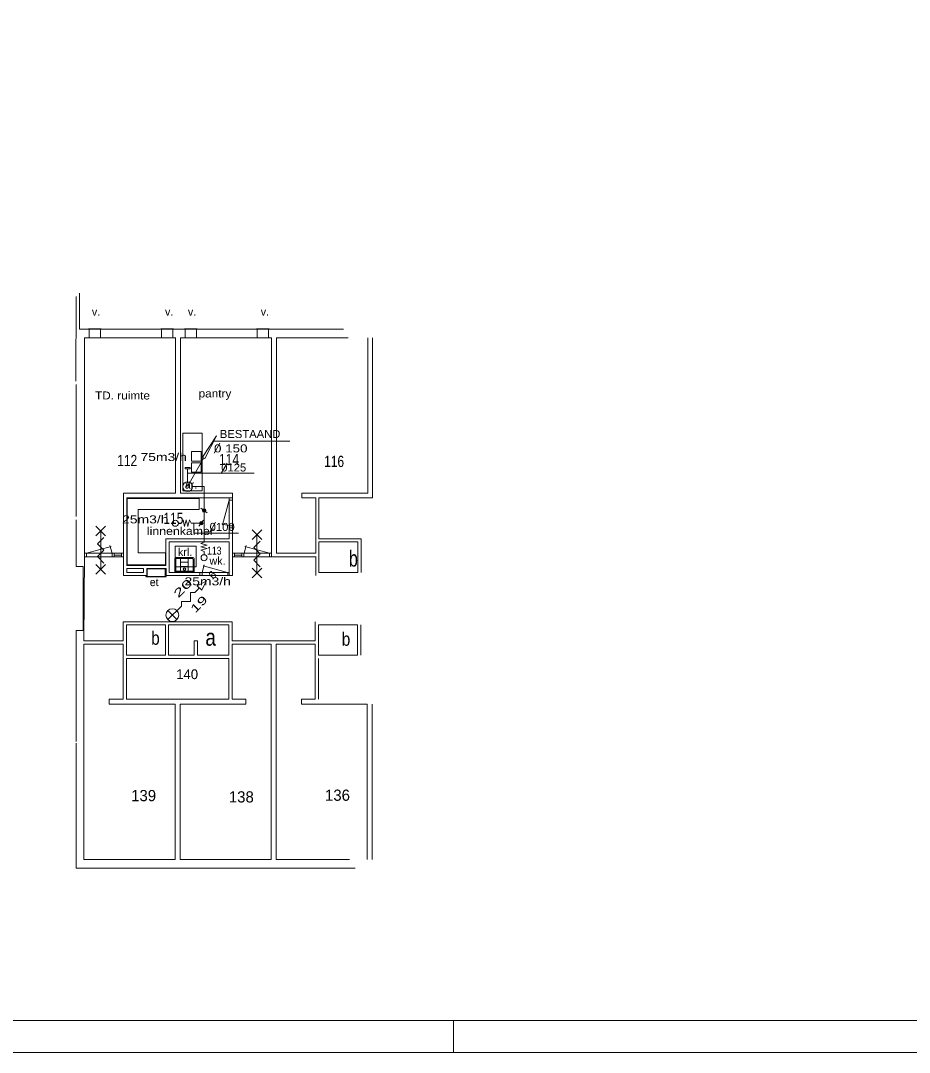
# Model space of a CAD drawing. Extents: x 295824 to 414724, y 24924 to 109024.
# Drawn here: x 359197 to 386960, y 24924 to 57152 of the extents above; entities that cross this region are included whole.
import ezdxf
from ezdxf.enums import TextEntityAlignment as Align

# ---------------------------------------------------------------- set-up
doc = ezdxf.new("R2010")
doc.units = 0
doc.header["$LTSCALE"] = 100
for name, color, linetype, lineweight in [('1', 7, 'Continuous', 13), ('24', 7, 'Continuous', 13), ('61', 7, 'Continuous', 13)]:
    doc.layers.add(name, color=color, linetype=linetype, lineweight=lineweight)

msp = doc.modelspace()

# ---------------------------------------------------------------- hatches: boundary and pattern name
at = {"layer": '24'}
for points in [[(364874.8, 41850, 1), (364983.4, 41850, 1)], [(364839.5, 41507.5, 1), (364839.5, 41398.9, 1)]]:
    msp.add_hatch(color=256, dxfattribs=at).paths.add_polyline_path(points)

# ---------------------------------------------------------------- linework, layer by layer
at = {"layer": '1'}
for p, q in [((364417.5, 42624), (364917.5, 43490)), ((372723.6, 24923.8), (372723.6, 25923.8)), ((304995.6, 24923.8), (414723.6, 24923.8))]:
    msp.add_line(p, q, dxfattribs=at)
msp.add_lwpolyline([(304995.6, 25923.8), (413723.6, 25923.8), (413723.6, 108023.8), (304995.6, 108023.8)], dxfattribs=at)
msp.add_lwpolyline([(365317.5, 44183), (364953.5, 43469), (364881.5, 43511)], close=True, dxfattribs=at)
msp.add_circle((364417.5, 42623.6), 50, dxfattribs=at)
at = {"layer": '24'}
for p, q in [((365423.5, 43957.8), (365239.1, 43638.5)), ((365240.5, 44010.8), (367601.3, 44010.8)), ((365649.4, 43330), (365465, 43010.7)), ((364412.7, 42748.9), (364412.7, 43166.1)), ((364431.5, 43018.1), (366491.3, 43018.1)), ((364566.3, 42595.3), (364929.1, 42595.3)), ((364929.1, 40914.6), (364929.1, 42595.3)), ((365020.7, 41779.2), (364829.1, 41920.8)), ((364570.4, 41453.2), (364929.1, 41453.2)), ((364768.7, 41361.6), (364910.3, 41553.1)), ((365287.7, 41489), (365103.4, 41169.7))]:
    msp.add_line(p, q, dxfattribs=at)
msp.add_lwpolyline([(364496.8, 43150.3), (364496.8, 43193.8), (364334.5, 43193.8), (364334.5, 43150.3)], close=True, dxfattribs=at)
for points in [[(364120.4, 41453.2), (364220.4, 41453.2), (364270.4, 41553.2), (364320.4, 41353.2), (364370.4, 41553.2), (364420.4, 41353.2), (364470.4, 41553.2), (364520.4, 41453.2), (364570.4, 41453.2)], [(364604.5, 41460.4), (364604.5, 41145.7), (366003.9, 41145.7)], [(364929.1, 40464.6), (364929.1, 40564.6), (364829.1, 40614.6), (365029.1, 40664.6), (364829.1, 40714.6), (365029.1, 40764.6), (364829.1, 40814.6), (364929.1, 40864.6), (364929.1, 40914.6)]]:
    msp.add_lwpolyline(points, dxfattribs=at)
for centre, radius in [((364412.7, 42595.3), 153.6), ((364929.1, 41850), 54.3), ((364028.7, 41453.2), 95), ((364839.5, 41453.2), 54.3), ((364929.1, 40372.9), 95)]:
    msp.add_circle(centre, radius, dxfattribs=at)
at = {"layer": '61'}
for p, q in [((360918.7, 45887.9), (360931.7, 48537.9)), ((361031.7, 48637.9), (361031.7, 47511.4)), ((361031.7, 47511.4), (369284.8, 47511.4)), ((361708, 47527.5), (361314.8, 47527.5)), ((361314.8, 47527.5), (361314.8, 47510)), ((361708, 47510), (361314.8, 47510)), ((361338.9, 47510), (361338.9, 47238.9)), ((361688.9, 47507.7), (361688.9, 47238.9)), ((361708, 47527.5), (361708, 47510)), ((363970.3, 47527.5), (363577.1, 47527.5)), ((363577.1, 47527.5), (363577.1, 47510)), ((363970.3, 47510), (363577.1, 47510)), ((363601.1, 47510), (363601.1, 47238.9)), ((363951.1, 47507.8), (363951.1, 47238.9)), ((363970.3, 47527.5), (363970.3, 47510)), ((364708.8, 47527.5), (364315.6, 47527.5)), ((364315.6, 47527.5), (364315.6, 47510)), ((364708.8, 47510), (364315.6, 47510)), ((364339.6, 47510), (364339.6, 47238.9)), ((364689.6, 47507.7), (364689.6, 47238.9)), ((364708.8, 47527.5), (364708.8, 47510)), ((366959.9, 47527.5), (366566.7, 47527.5)), ((366566.7, 47527.5), (366566.7, 47510)), ((366959.9, 47510), (366566.7, 47510)), ((366590.7, 47510), (366590.7, 47238.9)), ((366940.7, 47507.8), (366940.7, 47238.9)), ((366959.9, 47527.5), (366959.9, 47510)), ((361187.9, 47241.4), (361787.9, 47241.4)), ((361188.7, 40516.4), (361188.7, 47241.4)), ((363449.6, 47241.4), (364049, 47241.4)), ((363961.5, 47238.9), (363568.3, 47238.9)), ((367038.7, 47238.9), (364306.8, 47238.9)), ((367038.7, 47241.4), (364888.7, 47241.4)), ((366439.2, 47241.4), (367038.7, 47241.4)), ((366951.2, 47238.9), (366558, 47238.9)), ((367038.7, 40405.5), (367038.7, 47238.9)), ((367188.7, 47241.4), (369431.5, 47241.4)), ((370188.7, 47241.4), (370188.7, 42241.3)), ((360931.7, 45787.9), (360931.7, 41658.1)), ((362513.7, 42241.4), (365813.7, 42241.4)), ((362513.7, 40136.4), (362513.7, 42241.4)), ((364188.7, 42391.4), (365813.7, 42391.4)), ((364266.1, 42467.5), (364863.2, 42467.5)), ((365813.3, 42241.4), (365713.7, 42241.4)), ((365713.7, 42241.4), (365713.7, 40966.4)), ((365813.3, 42241.4), (365813.3, 41307.4)), ((365813.7, 42391.4), (365813.7, 42241.4)), ((368513.7, 40963.7), (368513.7, 42241.3)), ((370188.7, 42241.3), (368513.7, 42241.3)), ((365713.6, 42170.8), (365506.7, 41398.6)), ((365813.5, 42174.4), (365713.3, 42174.4)), ((361848.8, 41358), (361548.8, 41058)), ((361548.8, 41358), (361848.8, 41058)), ((365713.6, 41373.3), (365486.3, 41434.2)), ((365713.3, 41307.4), (365713.3, 41305.7)), ((365813.7, 41307.4), (365713.3, 41307.4)), ((365813.2, 41374.4), (365713.9, 41374.4)), ((365813.7, 41307.4), (365813.7, 40516.4)), ((361698.8, 40008), (361698.8, 41208)), ((365713.7, 40966.4), (363733.7, 40966.4)), ((363733.7, 40966.4), (363733.7, 40136.4)), ((366729.4, 41244.4), (366429.4, 40944.4)), ((366429.4, 41244.4), (366729.4, 40944.4)), ((366579.4, 39894.4), (366579.4, 41094.4)), ((368513.7, 40963.7), (369833.7, 40963.7)), ((369833.7, 39916.4), (369833.7, 40963.7)), ((361258.1, 40516.3), (362025.4, 40721.9)), ((362052.7, 40514.1), (361987.6, 40756.9)), ((364023.8, 40085.7), (364023.8, 40735.7)), ((364028.2, 40735.5), (364678.2, 40735.5)), ((364676.5, 40085.7), (364676.5, 40735.7)), ((366174.8, 40513.3), (366239.8, 40756.1)), ((366969.4, 40515.5), (366202.1, 40721.1)), ((361255.5, 40406.1), (361255.5, 40516.1)), ((362055.5, 40406.1), (362055.5, 40516.1)), ((362122.5, 40406.1), (362122.5, 40516.1)), ((362123.3, 40456.9), (362348, 40456.9)), ((362348, 40406.1), (362348, 40516.1)), ((362413.7, 40406.4), (362413.7, 39816.4)), ((364010.2, 40345.4), (364010.2, 39930.4)), ((364585.2, 40380.4), (364045.2, 40380.4)), ((364045.2, 39970.4), (364045.2, 40330.4)), ((364060.2, 40345.4), (364570.2, 40345.4)), ((364195.2, 39955.4), (364195.2, 40380.4)), ((364435.2, 39955.4), (364435.2, 40380.4)), ((364585.2, 40330.4), (364585.2, 39970.4)), ((364620.2, 39930.4), (364620.2, 40345.4)), ((365813.7, 39816.4), (365813.7, 40416.4)), ((365879.5, 40405.3), (365879.5, 40515.3)), ((366104.1, 40456.1), (365879.5, 40456.1)), ((366105, 40405.3), (366105, 40515.3)), ((366172, 40405.3), (366172, 40515.3)), ((366972, 40405.3), (366972, 40515.3)), ((367038.7, 40405.5), (368413.7, 40405.5)), ((368413.7, 40416.4), (368413.7, 39816.4)), ((361848.8, 40158), (361548.8, 39858)), ((361548.8, 40158), (361848.8, 39858)), ((363733.7, 40136.4), (362513.7, 40136.4)), ((362513.7, 39916.4), (362513.7, 40036.4)), ((363033.7, 40036.4), (362513.7, 40036.4)), ((363033.7, 40036.4), (363033.7, 39916.4)), ((363138, 40043), (363138, 39816.4)), ((363738, 40043), (363138, 40043)), ((363148.8, 39792.7), (363148.8, 40027.7)), ((363148.8, 40027.7), (363714.2, 40027.7)), ((363714.2, 39792.6), (363714.2, 40027.7)), ((363738, 40043), (363738, 39816.4)), ((364028.2, 40086.8), (364678.2, 40086.8)), ((364435.2, 40238.8), (364195.2, 40238.8)), ((364435.2, 40097.1), (364195.2, 40097.1)), ((364868.2, 39913.8), (364933.2, 40156.6)), ((365662.8, 39916), (364895.5, 40121.6)), ((366729.4, 40044.4), (366429.4, 39744.4)), ((366429.4, 40044.4), (366729.4, 39744.4)), ((362413.7, 39816.4), (363138, 39816.4)), ((362513.7, 39916.4), (363033.7, 39916.4)), ((363109.5, 39792.7), (363740.8, 39792.7)), ((363109.5, 39775.2), (363109.5, 39792.7)), ((363109.5, 39775.2), (363740.8, 39775.2)), ((363738, 39816.4), (365813.7, 39816.4)), ((363740.8, 39775.2), (363740.8, 39792.7)), ((364610.2, 39955.4), (364020.2, 39955.4)), ((364020.2, 39920.4), (364610.2, 39920.4)), ((364798.4, 39816.5), (364798.4, 39915.8)), ((364865.4, 39819.9), (364865.4, 39915.8)), ((365665.4, 39816.5), (365665.4, 39915.8)), ((363795.3, 38723), (364078.1, 38440.2)), ((369820.9, 38277.1), (369820.9, 37327.1)), ((368500.9, 37227.1), (368500.9, 35952.1)), ((370175.9, 30952.1), (370175.9, 35802.1)), ((360931.7, 30682.1), (360931.7, 34578.2)), ((367175.9, 30952.1), (369468.2, 30952.1)), ((369651.6, 30682.1), (360931.7, 30682.1))]:
    msp.add_line(p, q, dxfattribs=at)
for points in [[(361188.7, 47241.4), (364038.7, 47241.4), (364038.7, 42391.4), (362413.7, 42391.4), (362413.7, 40516.9)], [(364188.7, 42391.4), (364188.7, 47241.4), (364788.7, 47241.4)], [(370038.7, 47241.4), (370038.7, 42391.4), (367978.7, 42391.4), (367978.7, 42241.4), (368413.7, 42241.4), (368413.7, 40516.4), (367188.7, 40516.4), (367188.7, 47241.4)], [(364863.2, 42467.5), (364863.2, 44267.5), (364263.2, 44267.5), (364263.2, 42474.2)], [(360931.7, 41558.1), (360931.7, 40096.8), (361151.7, 40096.8), (361151.7, 38096.8), (360931.7, 38096.8), (360931.7, 34630.7)], [(361798.8, 40208), (361598.8, 40408), (361798.8, 40608), (361598.8, 40808), (361798.8, 41008)], [(363833.7, 40866.4), (365713.7, 40866.4), (365713.7, 39816.4)], [(365713.7, 39916.4), (363833.7, 39916.4), (363833.7, 40866.4)], [(366679.4, 40094.4), (366479.4, 40294.4), (366679.4, 40494.4), (366479.4, 40694.4), (366679.4, 40894.4)], [(368400.9, 38377.1), (368400.9, 37777.1), (365800.9, 37777.1), (365800.9, 38377.1), (362400.9, 38377.1), (362400.9, 37777.1), (361175.9, 37777.1), (361188.7, 40416.4)], [(363795.3, 38440.2), (364219.6, 38864.4), (364219.6, 39005.8), (364502.4, 39005.8), (364502.4, 39288.7), (364643.8, 39288.7), (364785.2, 39430.1)], [(370025.9, 30952.1), (370025.9, 35802.1), (367965.9, 35802.1), (367965.9, 35952.1), (368400.9, 35952.1), (368400.9, 37677.1), (367175.9, 37677.1), (367175.9, 30952.1)]]:
    msp.add_lwpolyline(points, dxfattribs=at)
for points in [[(364838.2, 43392.5), (364838.2, 43692.5), (364538.2, 43692.5), (364538.2, 43392.5)], [(364838.2, 43042.2), (364838.2, 43342.2), (364538.2, 43342.2), (364538.2, 43042.2)], [(364776.8, 42220.8), (364776.8, 41876.1), (362865.2, 41876.1), (362865.2, 40530.5), (363723.5, 40530.5), (363723.5, 40149.7), (362523.5, 40149.7), (362523.5, 42220.8)], [(368513.7, 40866.4), (369733.7, 40866.4), (369733.7, 39916.4), (368513.7, 39916.4)], [(361189.6, 40406.5), (361189.6, 40516.9), (362413.9, 40516.9), (362413.9, 40406.5)], [(367037.9, 40405.7), (367037.9, 40516.1), (365813.5, 40516.1), (365813.5, 40405.7)], [(364856, 39359.4), (364714.5, 39500.8), (364997.4, 39642.2)], [(362500.9, 37327.1), (363720.9, 37327.1), (363720.9, 38277.1), (362500.9, 38277.1)], [(363820.9, 37327.1), (364620.9, 37327.1), (364620.9, 37777.1), (364720.9, 37777.1), (364720.9, 37327.1), (365700.9, 37327.1), (365700.9, 38277.1), (363820.9, 38277.1)], [(368500.9, 37327.1), (369720.9, 37327.1), (369720.9, 38277.1), (368500.9, 38277.1)], [(361175.9, 30952.1), (364025.9, 30952.1), (364025.9, 35802.1), (361965.9, 35802.1), (361965.9, 35952.1), (362400.9, 35952.1), (362400.9, 37677.1), (361175.9, 37677.1)], [(367025.9, 30952.1), (364175.9, 30952.1), (364175.9, 35802.1), (366235.9, 35802.1), (366235.9, 35952.1), (365800.9, 35952.1), (365800.9, 37677.1), (367025.9, 37677.1)], [(362500.9, 35952.1), (365700.9, 35952.1), (365700.9, 37227.1), (362500.9, 37227.1)]]:
    msp.add_lwpolyline(points, close=True, dxfattribs=at)
for centre, radius in [((364315.2, 40020.4), 40), ((364315.2, 40020.4), 30), ((363936.7, 38581.6), 200)]:
    msp.add_circle(centre, radius, dxfattribs=at)
for centre, radius, start, end in [((364045.2, 40345.4), 35, 90, 180), ((364060.2, 40330.4), 15, 90, 180), ((364570.2, 40330.4), 15, 0, 90), ((364585.2, 40345.4), 35, 0, 90), ((364060.2, 39970.4), 15, 180, 270), ((364570.2, 39970.4), 15, 270, 0), ((364020.2, 39945.4), 10, 90, 180), ((364020.2, 39930.4), 10, 180, 270), ((364610.2, 39945.4), 10, 0, 90), ((364610.2, 39930.4), 10, 270, 0)]:
    msp.add_arc(centre, radius, start, end, dxfattribs=at)

# ---------------------------------------------------------------- texts
at = {"layer": '24'}
for s, width, p in [('BESTAAND', 1.05, (365419.2, 44114.8)), ('0 150', 1.25, (365237.4, 43664.8)), ('75m3/h', 1.3, (362941.1, 43395.8)), ('0125', 1.05, (365463.3, 43068.5)), ('25m3/h', 1.3, (362365.7, 41447.8)), ('0100', 1.05, (365101.6, 41211.8)), ('25m3/h', 1.3, (364315.5, 39512.5))]:
    msp.add_text(s, height=250, dxfattribs=dict(at, width=width)).set_placement(p)
at = {"layer": '61'}
for s, height, p in [('v.', 250, (361421.8, 47933.8)), ('v.', 250, (363708, 47933.8)), ('v.', 250, (364422.6, 47933.8)), ('v.', 250, (366697.6, 47933.8)), ('ar.', 250, (364324.1, 42531.2)), ('krl.', 250, (364111.2, 40428.5)), ('wk.', 250, (365097.5, 40152.8)), ('et', 250, (363229.6, 39487.7)), ('139', 350, (362648.1, 32769.3)), ('138', 350, (365700.7, 32729.2)), ('136', 350, (368704, 32781.5))]:
    msp.add_text(s, height=height, dxfattribs=at).set_placement(p)
for s, height, width, p in [('TD. ruimte', 250, 1.1, (361521.4, 45317.3)), ('pantry', 250, 1.1, (364757, 45381.3)), ('112', 350, 0.8, (362213.6, 43237.8)), ('114', 350, 0.8, (365394.9, 43267.4)), ('116', 350, 0.8, (368677.5, 43208.3)), ('115', 350, 0.8, (363656.4, 41429.4)), ('linnenkamer', 250, 1.15, (363141.5, 41083.7)), ('113', 250, 0.8, (365024.3, 40471.1)), ('b', 500, 0.75, (369452.3, 40097.6))]:
    msp.add_text(s, height=height, dxfattribs=dict(at, width=width)).set_placement(p)
msp.add_text('6', height=250, rotation=45, dxfattribs=at).set_placement((365211.9, 39688.1))
for s, width, p in [('20', 1.75, (364121.9, 39104.1)), ('19', 1.55, (364650.4, 38631.8))]:
    msp.add_text(s, height=250, rotation=45, dxfattribs=dict(at, width=width)).set_placement(p)
at = {"layer": '61', "width": 0.85}
for s, height, p in [('b', 420, (363407, 37655.5)), ('a', 525, (365132.8, 37625.8)), ('b', 420, (369361.8, 37622.6))]:
    msp.add_text(s, height=height, dxfattribs=at).set_placement(p, align=Align.CENTER)
at = {"layer": '61'}
msp.add_text('140', height=306.2, dxfattribs=at).set_placement((364399, 36582.3), align=Align.CENTER)

doc.saveas('drawing.dxf')
